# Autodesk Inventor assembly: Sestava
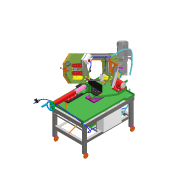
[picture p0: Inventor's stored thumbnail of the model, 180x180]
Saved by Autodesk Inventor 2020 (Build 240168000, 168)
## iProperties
Created: 2025-03
Part Number: Sestava
Document SubType Name: Assembly
Designer: doma
Mass: 207776 g
Surface Area: 115474 cm^2
Volume: 32122.7 cm^3
Density: 6.4682 g/cm^3
Author: doma
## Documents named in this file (41)
- C:\Users\doma\Desktop\Pásovka záloha\Workgroups\NotInProject\Sestava.iam
- C:\Users\doma\Documents\Inventor\Content Center Files\R2020\cs-CZ\ISO 4762(2)\ISO 4762 - M5 x 10ISO.ipt
- C:\Users\doma\Desktop\Pásovka záloha\Workgroups\NotInProject\Zajištění čepu.ipt
- C:\Users\doma\Desktop\Pásovka záloha\Workgroups\NotInProject\Víčko čepu.ipt
- C:\Users\doma\Documents\Inventor\Content Center Files\R2020\cs-CZ\CSN 02 1740\CSN 02 1740 - 6.ipt
- C:\Users\doma\Desktop\Pásovka záloha\Workgroups\NotInProject\Hydraulický válec píst.ipt
- C:\Users\doma\Desktop\Pásovka záloha\Workgroups\NotInProject\Hydraulický válec tělo.ipt
- C:\Users\doma\Desktop\Pásovka záloha\Workgroups\NotInProject\Kontakt spínače.ipt
- C:\Users\doma\Desktop\Pásovka záloha\Workgroups\NotInProject\Elektroinstalace.ipt
- C:\Users\doma\Desktop\Pásovka záloha\Workgroups\NotInProject\T.ipt
- C:\Users\doma\Desktop\Pásovka záloha\Workgroups\NotInProject\Ventil.ipt
- C:\Users\doma\Desktop\Pásovka záloha\Workgroups\NotInProject\Hadice chlazení 5.ipt
- C:\Users\doma\Desktop\Pásovka záloha\Workgroups\NotInProject\Svazek 2.ipt
- C:\Users\doma\Desktop\Pásovka záloha\Workgroups\NotInProject\Hadice chlazení 2_1.ipt
- C:\Users\doma\Desktop\Pásovka záloha\Workgroups\NotInProject\Kabel 3.ipt
- C:\Users\doma\Desktop\Pásovka záloha\Workgroups\NotInProject\Hadice chlazení 1.ipt
- C:\Users\doma\Documents\Inventor\Content Center Files\R2020\cs-CZ\CSN 02 1741\CSN 02 1741 - 5.ipt
- C:\Users\doma\Documents\Inventor\Content Center Files\R2020\cs-CZ\ISO 4762(2)\ISO 4762 - M8 x 30ISO.ipt
- C:\Users\doma\Documents\Inventor\Content Center Files\R2020\cs-CZ\CSN 02 1703\CSN 02 1703 - 8,4.ipt
- C:\Users\doma\Documents\Inventor\Content Center Files\R2020\cs-CZ\ISO 4762(2)\ISO 4762 - M6 x 20ISO.ipt
- C:\Users\doma\Documents\Inventor\Content Center Files\R2020\cs-CZ\CSN 02 1741\CSN 02 1741 - 10.ipt
- C:\Users\doma\Documents\Inventor\Content Center Files\R2020\cs-CZ\CSN 02 1703\CSN 02 1703 - 10,5.ipt
- C:\Users\doma\Documents\Inventor\Content Center Files\R2020\cs-CZ\ISO 4032(2)\ISO 4032 - M10 - ISO.ipt
- C:\Users\doma\Documents\Inventor\Content Center Files\R2020\cs-CZ\ISO 4762(2)\ISO 4762 - M10 x 80ISO.ipt
- C:\Users\doma\Documents\Inventor\Content Center Files\R2020\cs-CZ\CSN 02 1703\CSN 02 1703 - 5,3.ipt
- C:\Users\doma\Documents\Inventor\Content Center Files\R2020\cs-CZ\ISO 4032(2)\ISO 4032 - M5 - ISO.ipt
- C:\Users\doma\Documents\Inventor\Content Center Files\R2020\cs-CZ\ISO 4762(2)\ISO 4762 - M5 x 30ISO.ipt
- C:\Users\doma\Documents\Inventor\Content Center Files\R2020\cs-CZ\ISO 4762(2)\ISO 4762 - M8 x 35ISO.ipt
- C:\Users\doma\Documents\Inventor\Content Center Files\R2020\cs-CZ\ISO 4762(2)\ISO 4762 - M12 x 45ISO.ipt
- C:\Users\doma\Documents\Inventor\Content Center Files\R2020\cs-CZ\CSN 02 1741\CSN 02 1741 - 12.ipt
- C:\Users\doma\Documents\Inventor\Content Center Files\R2020\cs-CZ\ISO 4762(2)\ISO 4762 - M12 x 55ISO.ipt
- C:\Users\doma\Desktop\Pásovka záloha\Workgroups\NotInProject\Podsestava horní rameno.iam
- C:\Users\doma\Desktop\Pásovka záloha\Workgroups\NotInProject\Podsestava svěrák.iam
- C:\Users\doma\Desktop\Pásovka záloha\Workgroups\NotInProject\Podsestava kotvení.iam
- C:\Users\doma\Desktop\Pásovka záloha\Workgroups\NotInProject\Podsestava podvozek.iam
- C:\Users\doma\Desktop\Pásovka záloha\Workgroups\NotInProject\Koncový spínač.ipt
- C:\Users\doma\Desktop\Pásovka záloha\Workgroups\NotInProject\Mezikus koncový spínač.ipt
- C:\Users\doma\Desktop\Pásovka záloha\Workgroups\NotInProject\Kabel 4.ipt
- C:\Users\doma\Documents\Inventor\Content Center Files\R2020\cs-CZ\ISO 4762(2)\ISO 4762 - M5 x 12ISO.ipt
- C:\Users\doma\Documents\Inventor\Content Center Files\R2020\cs-CZ\ISO 4762(2)\ISO 4762 - M5 x 25ISO.ipt
- C:\Users\doma\Documents\Inventor\Content Center Files\R2020\cs-CZ\ISO 4762(2)\ISO 4762 - M5 x 35ISO.ipt
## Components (61 placed, 40 different names)
1. Hydraulický válec tělo:1 — Proti sobě:363
2. Ventil:1 — Proti sobě:289, Proti sobě:290
3. T:2 — Proti sobě:291, Proti sobě:292, Proti sobě:294, Proti sobě:295, Proti sobě:298, Proti sobě:306, Proti sobě:309
4. Hadice chlazení 5:1 — Proti sobě:289, Proti sobě:290, Proti sobě:291, Proti sobě:292
5. Svazek 2:1 — Proti sobě:296, Proti sobě:297
6. Hadice chlazení 2_1:1 — Proti sobě:294, Proti sobě:295, Proti sobě:296, Proti sobě:297, Proti sobě:298
7. Kabel 3:1
8. Hadice chlazení 1:1 — Proti sobě:306, Proti sobě:309
9. CSN 02 1741 10:8 — Proti sobě:364
10. CSN 02 1703 10,5:1 — Proti sobě:366, Stejný směr:75
11. ISO 4032 M10:1
12. ISO 4762 M10 x 80:1 — Proti sobě:365, Proti sobě:366
13. ISO 4762 M8 x 35:1
14. ISO 4762 M8 x 35:2
15. ISO 4762 M8 x 35:3
16. ISO 4762 M8 x 35:4
17. ISO 4762 M12 x 45:1
18. ISO 4762 M12 x 45:2
19. ISO 4762 M12 x 45:3
20. ISO 4762 M12 x 45:4
21. CSN 02 1741 12:9
22. ISO 4762 M12 x 55:1 — Proti sobě:362
23. Hydraulický válec píst:1
24. ISO 4762 M8 x 30:1
25. CSN 02 1703 8,4:1
26. Kontakt spínače:1 — Proti sobě:371
27. CSN 02 1703 5,3:2
28. ISO 4762 M5 x 30:4
29. ISO 4032 M5:1
30. CSN 02 1703 5,3:1
31. CSN 02 1741 5:1
32. Podsestava horní rameno:1 [sub-assembly] — Proti sobě:369
33. CSN 02 1740 6:2
34. ISO 4762 M6 x 20:1
35. CSN 02 1740 6:3
36. ISO 4762 M6 x 20:3
37. CSN 02 1740 6:4
38. ISO 4762 M6 x 20:2
39. Víčko čepu:1 — Proti sobě:368
40. Zajištění čepu:1
41. Podsestava svěrák:1 [sub-assembly] — Proti sobě:362
42. Podsestava kotvení:1 [sub-assembly] — Proti sobě:361, Proti sobě:363, Proti sobě:364, Proti sobě:365, Stejný směr:75, Proti sobě:367
43. Elektroinstalace:1
44. Podsestava podvozek:1 [sub-assembly] — Proti sobě:361
45. Koncový spínač:1
46. Mezikus koncový spínač:1
47. Kabel 4:1
48. CSN 02 1741 5:2
49. CSN 02 1741 5:3
50. CSN 02 1741 5:4
51. CSN 02 1741 5:5
52. CSN 02 1741 5:6
53. CSN 02 1741 5:7
54. ISO 4762 M5 x 35:1
55. ISO 4762 M5 x 35:2
56. ISO 4762 M5 x 12:3
57. ISO 4762 M5 x 12:4
58. ISO 4762 M5 x 10:2
59. ISO 4762 M5 x 10:3
60. ISO 4032 M5:2 — Proti sobě:370
61. ISO 4762 M5 x 25:1 — Proti sobě:370, Proti sobě:371
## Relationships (23: Mate 22, Flush 1)
- Proti sobě:289 [Mate]: Ventil:1 ↔ Hadice chlazení 5:1
- Proti sobě:290 [Mate]: Ventil:1 ↔ Hadice chlazení 5:1
- Proti sobě:291 [Mate]: T:2 ↔ Hadice chlazení 5:1
- Proti sobě:292 [Mate]: T:2 ↔ Hadice chlazení 5:1
- Proti sobě:294 [Mate]: T:2 ↔ Hadice chlazení 2_1:1
- Proti sobě:295 [Mate]: T:2 ↔ Hadice chlazení 2_1:1
- Proti sobě:296 [Mate]: Svazek 2:1 ↔ Hadice chlazení 2_1:1
- Proti sobě:297 [Mate]: Svazek 2:1 ↔ Hadice chlazení 2_1:1
- Proti sobě:298 [Mate]: T:2 ↔ Hadice chlazení 2_1:1
- Proti sobě:306 [Mate]: T:2 ↔ Hadice chlazení 1:1
- Proti sobě:309 [Mate]: T:2 ↔ Hadice chlazení 1:1
- Proti sobě:361 [Mate]: Podsestava kotvení:1 ↔ Podsestava podvozek:1
- Proti sobě:362 [Mate]: ISO 4762 M12 x 55:1 ↔ Podsestava svěrák:1
- Proti sobě:363 [Mate]: Hydraulický válec tělo:1 ↔ Podsestava kotvení:1
- Proti sobě:364 [Mate]: CSN 02 1741 10:8 ↔ Podsestava kotvení:1
- Proti sobě:365 [Mate]: ISO 4762 M10 x 80:1 ↔ Podsestava kotvení:1
- Proti sobě:366 [Mate]: CSN 02 1703 10,5:1 ↔ ISO 4762 M10 x 80:1
- Stejný směr:75 [Flush]: CSN 02 1703 10,5:1 ↔ Podsestava kotvení:1
- Proti sobě:367 [Mate]: Podsestava kotvení:1
- Proti sobě:368 [Mate]: Víčko čepu:1
- Proti sobě:369 [Mate]: Podsestava horní rameno:1
- Proti sobě:370 [Mate]: ISO 4032 M5:2 ↔ ISO 4762 M5 x 25:1
- Proti sobě:371 [Mate]: Kontakt spínače:1 ↔ ISO 4762 M5 x 25:1
